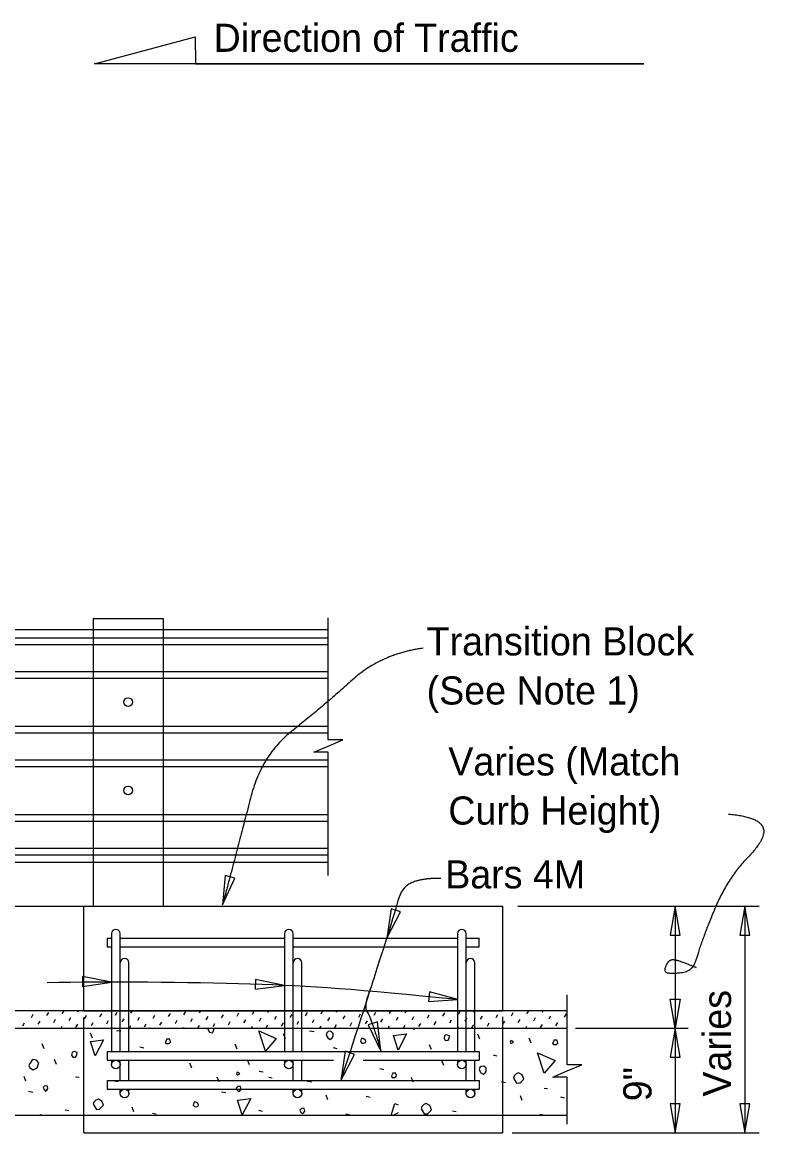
# Model space of a CAD drawing. Extents: x 21526.6 to 21598.7, y 56118.1 to 56155.9.
# Drawn here: x 21561.97 to 21567.29, y 56133.58 to 56141.55 of the extents above; entities that cross this region are included whole.
import ezdxf

# ---------------------------------------------------------------- set-up
doc = ezdxf.new("R2010")
doc.units = 0
for name, color, linetype in [('AdhocPoint_dp', 7, 'Continuous'), ('Border', 7, 'Continuous'), ('Patterning', 7, 'Continuous'), ('PlotBorder_dp', 7, 'Continuous'), ('SheetBorder_dp', 7, 'Continuous'), ('SheetLines_dp', 7, 'Continuous'), ('SubStrConc', 7, 'Continuous'), ('SubStrConc_h', 7, 'Continuous')]:
    doc.layers.add(name, color=color, linetype=linetype)

msp = doc.modelspace()

# ---------------------------------------------------------------- linework, layer by layer
at = {"layer": 'AdhocPoint_dp'}
for p, q in [((21554.3018, 56135.21), (21562.4118, 56135.21)), ((21565.8764, 56134.4601), (21554.3018, 56134.4601)), ((21554.3018, 56134.3351), (21565.8764, 56134.3351)), ((21565.8764, 56133.71), (21559.5217, 56133.71))]:
    msp.add_line(p, q, dxfattribs=at)
at = {"layer": 'Patterning'}
for p, q in [((21562.4788, 56137.2725), (21562.4788, 56135.21)), ((21562.4788, 56137.2725), (21562.9788, 56137.2725)), ((21562.9788, 56137.2725), (21562.9788, 56135.21)), ((21562.0356, 56134.4123), (21562.0485, 56134.4347)), ((21562.1462, 56134.4253), (21562.1592, 56134.4477)), ((21562.2568, 56134.4383), (21562.2695, 56134.4601)), ((21562.3057, 56134.3894), (21562.3186, 56134.4118)), ((21562.3675, 56134.4512), (21562.3726, 56134.4601)), ((21562.4163, 56134.4024), (21562.4293, 56134.4248)), ((21562.5269, 56134.4154), (21562.5399, 56134.4377)), ((21562.6376, 56134.4283), (21562.6505, 56134.4507)), ((21562.6864, 56134.3795), (21562.6994, 56134.4019)), ((21562.7482, 56134.4413), (21562.7591, 56134.4601)), ((21562.797, 56134.3925), (21562.81, 56134.4148)), ((21562.8588, 56134.4542), (21562.8622, 56134.4601)), ((21562.9077, 56134.4054), (21562.9206, 56134.4278)), ((21563.0183, 56134.4184), (21563.0312, 56134.4408)), ((21563.1289, 56134.4313), (21563.1419, 56134.4537)), ((21563.1778, 56134.3825), (21563.1907, 56134.4049)), ((21563.2396, 56134.4443), (21563.2487, 56134.4601)), ((21563.2884, 56134.3955), (21563.3013, 56134.4179)), ((21563.3502, 56134.4573), (21563.3518, 56134.4601)), ((21563.399, 56134.4084), (21563.412, 56134.4308)), ((21563.5097, 56134.4214), (21563.5226, 56134.4438)), ((21563.6203, 56134.4344), (21563.6332, 56134.4568)), ((21563.6691, 56134.3855), (21563.6821, 56134.4079)), ((21563.7309, 56134.4473), (21563.7383, 56134.4601)), ((21563.7798, 56134.3985), (21563.7927, 56134.4209)), ((21563.8904, 56134.4115), (21563.9033, 56134.4338)), ((21564.001, 56134.4244), (21564.014, 56134.4468)), ((21564.1116, 56134.4374), (21564.1246, 56134.4598)), ((21564.1605, 56134.3885), (21564.1734, 56134.4109)), ((21564.2223, 56134.4503), (21564.2279, 56134.4601)), ((21564.2711, 56134.4015), (21564.2841, 56134.4239)), ((21564.3817, 56134.4145), (21564.3947, 56134.4369)), ((21564.4924, 56134.4274), (21564.5053, 56134.4498)), ((21564.5412, 56134.3786), (21564.5542, 56134.401)), ((21564.603, 56134.4404), (21564.6144, 56134.4601)), ((21564.6518, 56134.3916), (21564.6648, 56134.414)), ((21564.7151, 56134.4443), (21564.7243, 56134.4601)), ((21564.764, 56134.3955), (21564.7769, 56134.4179)), ((21564.8258, 56134.4573), (21564.8274, 56134.4601)), ((21564.8746, 56134.4084), (21564.8876, 56134.4308)), ((21564.9852, 56134.4214), (21564.9982, 56134.4438)), ((21565.0959, 56134.4344), (21565.1088, 56134.4568)), ((21565.1447, 56134.3855), (21565.1577, 56134.4079)), ((21565.2065, 56134.4473), (21565.2139, 56134.4601)), ((21565.2553, 56134.3985), (21565.2683, 56134.4209)), ((21565.366, 56134.4115), (21565.3789, 56134.4338)), ((21565.4766, 56134.4244), (21565.4896, 56134.4468)), ((21565.5872, 56134.4374), (21565.6002, 56134.4598)), ((21565.6361, 56134.3885), (21565.649, 56134.4109)), ((21565.6979, 56134.4503), (21565.7035, 56134.4601)), ((21565.7467, 56134.4015), (21565.7597, 56134.4239)), ((21565.8573, 56134.4145), (21565.8703, 56134.4369)), ((21561.9738, 56134.3505), (21561.9867, 56134.3729)), ((21562.0844, 56134.3635), (21562.0974, 56134.3859)), ((21562.145, 56134.3351), (21562.1462, 56134.3371)), ((21562.195, 56134.3765), (21562.208, 56134.3989)), ((21562.2482, 56134.3351), (21562.2568, 56134.35)), ((21562.3545, 56134.3406), (21562.3675, 56134.363)), ((21562.4651, 56134.3536), (21562.4781, 56134.376)), ((21562.5758, 56134.3665), (21562.5887, 56134.3889)), ((21562.6346, 56134.3351), (21562.6376, 56134.3401)), ((21562.7378, 56134.3351), (21562.7482, 56134.353)), ((21562.8459, 56134.3436), (21562.8588, 56134.366)), ((21562.9565, 56134.3566), (21562.9695, 56134.379)), ((21563.0671, 56134.3695), (21563.0801, 56134.3919)), ((21563.1243, 56134.3351), (21563.1289, 56134.3431)), ((21563.2274, 56134.3351), (21563.2396, 56134.3561)), ((21563.3372, 56134.3466), (21563.3502, 56134.369)), ((21563.4479, 56134.3596), (21563.4608, 56134.382)), ((21563.5585, 56134.3726), (21563.5714, 56134.395)), ((21563.6139, 56134.3351), (21563.6203, 56134.3461)), ((21563.718, 56134.3367), (21563.7309, 56134.3591)), ((21563.8286, 56134.3497), (21563.8415, 56134.372)), ((21563.9392, 56134.3626), (21563.9522, 56134.385)), ((21564.0004, 56134.3351), (21564.001, 56134.3362)), ((21564.0499, 56134.3756), (21564.0628, 56134.398)), ((21564.1035, 56134.3351), (21564.1116, 56134.3491)), ((21564.2093, 56134.3397), (21564.2223, 56134.3621)), ((21564.32, 56134.3527), (21564.3329, 56134.3751)), ((21564.4306, 56134.3656), (21564.4435, 56134.388)), ((21564.49, 56134.3351), (21564.4924, 56134.3392)), ((21564.5931, 56134.3351), (21564.603, 56134.3522)), ((21564.703, 56134.3351), (21564.7151, 56134.3561)), ((21564.8128, 56134.3466), (21564.8258, 56134.369)), ((21564.9234, 56134.3596), (21564.9364, 56134.382)), ((21565.0341, 56134.3726), (21565.047, 56134.395)), ((21565.0895, 56134.3351), (21565.0959, 56134.3461)), ((21565.1935, 56134.3367), (21565.2065, 56134.3591)), ((21565.3042, 56134.3497), (21565.3171, 56134.372)), ((21565.4148, 56134.3626), (21565.4278, 56134.385)), ((21565.476, 56134.3351), (21565.4766, 56134.3362)), ((21565.5254, 56134.3756), (21565.5384, 56134.398)), ((21565.5791, 56134.3351), (21565.5872, 56134.3491)), ((21565.6849, 56134.3397), (21565.6979, 56134.3621)), ((21565.7955, 56134.3527), (21565.8085, 56134.3751)), ((21562.4721, 56134.2625), (21562.458, 56134.2979)), ((21562.6448, 56134.3185), (21562.6766, 56134.315)), ((21563.8568, 56134.259), (21563.8427, 56134.2944)), ((21564.0294, 56134.315), (21564.0613, 56134.3114)), ((21565.2489, 56134.2557), (21565.2347, 56134.291)), ((21565.6176, 56134.2282), (21565.6035, 56134.2636)), ((21562.1263, 56134.1877), (21562.1121, 56134.223)), ((21562.8127, 56134.2001), (21562.841, 56134.193)), ((21563.511, 56134.1841), (21563.4968, 56134.2195)), ((21564.1974, 56134.1965), (21564.2257, 56134.1894)), ((21564.903, 56134.1808), (21564.8889, 56134.2161)), ((21562.214, 56134.0752), (21562.1999, 56134.1105)), ((21563.1862, 56134.0491), (21563.172, 56134.0845)), ((21563.5987, 56134.0716), (21563.5846, 56134.107)), ((21564.9908, 56134.0683), (21564.9767, 56134.1036)), ((21565.3441, 56134.1447), (21565.3724, 56134.1376)), ((21563.6672, 56134.0268), (21563.6973, 56134.0215)), ((21564.5329, 56134.0454), (21564.5612, 56134.0384)), ((21561.9955, 56133.9543), (21561.9831, 56133.9879)), ((21562.3519, 56133.9868), (21562.3767, 56133.9832)), ((21562.6277, 56133.9585), (21562.6578, 56133.9532)), ((21563.3802, 56133.9508), (21563.3678, 56133.9844)), ((21563.7366, 56133.9832), (21563.7614, 56133.9797)), ((21564.0124, 56133.955), (21564.0424, 56133.9497)), ((21564.7722, 56133.9474), (21564.7598, 56133.981)), ((21565.4045, 56133.9516), (21565.4345, 56133.9463)), ((21562.0143, 56133.8825), (21562.0443, 56133.8772)), ((21563.399, 56133.8789), (21563.429, 56133.8736)), ((21564.1609, 56133.8206), (21564.1485, 56133.8542)), ((21564.4349, 56133.8471), (21564.4632, 56133.8401)), ((21565.5529, 56133.8173), (21565.5406, 56133.8508)), ((21565.7105, 56133.9057), (21565.7353, 56133.9022)), ((21565.8269, 56133.8438), (21565.8552, 56133.8367)), ((21562.7705, 56133.7357), (21562.7581, 56133.7693)), ((21562.2777, 56133.7499), (21562.3042, 56133.7446)), ((21562.9035, 56133.7251), (21562.93, 56133.7198)), ((21563.1969, 56133.71), (21563.1963, 56133.7116)), ((21563.6624, 56133.7464), (21563.6889, 56133.7411)), ((21564.2882, 56133.7216), (21564.3147, 56133.7163)), ((21565.0544, 56133.743), (21565.0809, 56133.7377)), ((21565.6802, 56133.7183), (21565.7067, 56133.713))]:
    msp.add_line(p, q, dxfattribs=at)
for points in [[(21563.3008, 56134.3351), (21563.2988, 56134.3291), (21563.3024, 56134.322)], [(21563.3024, 56134.322), (21563.3112, 56134.3061), (21563.3324, 56134.3026), (21563.3413, 56134.3185), (21563.3448, 56134.3326), (21563.3424, 56134.3351)], [(21564.7764, 56134.3351), (21564.7744, 56134.3291), (21564.7779, 56134.322)], [(21562.4929, 56134.1357), (21562.4593, 56134.24), (21562.553, 56134.2524), (21562.4929, 56134.1357)], [(21563.0001, 56134.2248), (21563.0213, 56134.2248), (21563.0319, 56134.2354), (21563.0266, 56134.2549), (21563.0036, 56134.2566), (21563.0001, 56134.246), (21562.9948, 56134.2372), (21563.0001, 56134.2248), (21562.9965, 56134.2283)], [(21563.7121, 56134.1696), (21563.6644, 56134.3163), (21563.7899, 56134.2615), (21563.7121, 56134.1696)], [(21564.1486, 56134.2859), (21564.1592, 56134.2647), (21564.1769, 56134.2541), (21564.191, 56134.2647), (21564.1981, 56134.2753), (21564.1981, 56134.2965), (21564.1822, 56134.3124), (21564.1627, 56134.3106), (21564.1539, 56134.3018), (21564.1486, 56134.2859)], [(21564.4044, 56134.2281), (21564.4168, 56134.2263), (21564.4292, 56134.2316), (21564.4327, 56134.2423), (21564.4274, 56134.2511), (21564.4168, 56134.2582), (21564.4044, 56134.2635), (21564.3973, 56134.2493), (21564.3938, 56134.2387), (21564.4044, 56134.2281)], [(21564.6643, 56134.1779), (21564.6307, 56134.2822), (21564.7244, 56134.2945), (21564.6643, 56134.1779)], [(21564.9933, 56134.2627), (21565.0022, 56134.2468), (21565.0216, 56134.2485), (21565.0304, 56134.2609), (21565.0322, 56134.2803), (21565.0198, 56134.2856), (21565.011, 56134.2874), (21565.0004, 56134.2839), (21564.9968, 56134.2803), (21564.9933, 56134.2627)], [(21565.4713, 56134.2251), (21565.4908, 56134.2339), (21565.4837, 56134.241), (21565.4713, 56134.2463), (21565.466, 56134.2339), (21565.4713, 56134.2251)], [(21565.7768, 56134.2179), (21565.798, 56134.2179), (21565.8086, 56134.2285), (21565.8033, 56134.248), (21565.7804, 56134.2497), (21565.7768, 56134.2391), (21565.7715, 56134.2303), (21565.7768, 56134.2179), (21565.7733, 56134.2215)], [(21562.3237, 56134.1423), (21562.3325, 56134.1264), (21562.3519, 56134.1282), (21562.3608, 56134.1406), (21562.3625, 56134.16), (21562.3502, 56134.1653), (21562.3413, 56134.1671), (21562.3307, 56134.1636), (21562.3272, 56134.16), (21562.3237, 56134.1423)], [(21562.0238, 56134.0498), (21562.0467, 56134.0374), (21562.0768, 56134.0498), (21562.0892, 56134.0869), (21562.0715, 56134.1046), (21562.0485, 56134.1099), (21562.0379, 56134.1028), (21562.0255, 56134.0834), (21562.0167, 56134.0675), (21562.0238, 56134.0498)], [(21565.7117, 56134.0122), (21565.664, 56134.1589), (21565.7895, 56134.1041), (21565.7117, 56134.0122)], [(21563.5103, 56133.998), (21563.5298, 56134.0068), (21563.5227, 56134.0139), (21563.5103, 56134.0192), (21563.505, 56134.0068), (21563.5103, 56133.998)], [(21564.6215, 56133.9816), (21564.6427, 56133.9816), (21564.6533, 56133.9922), (21564.648, 56134.0116), (21564.625, 56134.0134), (21564.6215, 56134.0028), (21564.6162, 56133.994), (21564.6215, 56133.9816), (21564.618, 56133.9851)], [(21565.2454, 56134.0365), (21565.256, 56134.0152), (21565.2736, 56134.0046), (21565.2878, 56134.0152), (21565.2948, 56134.0259), (21565.2948, 56134.0471), (21565.2789, 56134.063), (21565.2595, 56134.0612), (21565.2507, 56134.0524), (21565.2454, 56134.0365)], [(21565.4907, 56133.9776), (21565.5137, 56133.9404), (21565.5366, 56133.9422), (21565.5455, 56133.9511), (21565.5649, 56133.9705), (21565.5526, 56134.0005), (21565.5278, 56134.0147), (21565.5101, 56134.0076), (21565.496, 56133.9935), (21565.4907, 56133.9776)], [(21562.1257, 56133.8949), (21562.1363, 56133.8842), (21562.1469, 56133.8913), (21562.1539, 56133.9019), (21562.1504, 56133.9196), (21562.1416, 56133.9214), (21562.1292, 56133.9196), (21562.1186, 56133.909), (21562.1257, 56133.8949)], [(21563.5103, 56133.8913), (21563.5209, 56133.8807), (21563.5316, 56133.8878), (21563.5386, 56133.8984), (21563.5351, 56133.9161), (21563.5262, 56133.9178), (21563.5139, 56133.9161), (21563.5033, 56133.9055), (21563.5103, 56133.8913)], [(21562.4785, 56133.7897), (21562.5015, 56133.7526), (21562.5245, 56133.7544), (21562.5333, 56133.7632), (21562.5528, 56133.7827), (21562.5404, 56133.8127), (21562.5156, 56133.8269), (21562.498, 56133.8198), (21562.4838, 56133.8056), (21562.4785, 56133.7897)], [(21563.2051, 56133.7723), (21563.2175, 56133.7705), (21563.2299, 56133.7758), (21563.2334, 56133.7864), (21563.2281, 56133.7952), (21563.2175, 56133.8023), (21563.2051, 56133.8076), (21563.1981, 56133.7935), (21563.1945, 56133.7829), (21563.2051, 56133.7723)], [(21563.547, 56133.7141), (21563.5134, 56133.8184), (21563.6071, 56133.8308), (21563.547, 56133.7141)], [(21564.6141, 56133.71), (21564.6405, 56133.7959), (21564.6652, 56133.7861)], [(21564.8288, 56133.7569), (21564.8518, 56133.7198), (21564.8748, 56133.7216), (21564.8836, 56133.7304), (21564.9031, 56133.7499), (21564.8907, 56133.7799), (21564.8659, 56133.794), (21564.8483, 56133.787), (21564.8341, 56133.7728), (21564.8288, 56133.7569)], [(21562.1099, 56133.71), (21562.1009, 56133.7145), (21562.0934, 56133.71)], [(21563.4875, 56133.71), (21563.4856, 56133.711), (21563.484, 56133.71)], [(21563.9669, 56133.7339), (21563.9775, 56133.7233), (21563.9881, 56133.7304), (21563.9951, 56133.741), (21563.9916, 56133.7586), (21563.9828, 56133.7604), (21563.9704, 56133.7586), (21563.9598, 56133.748), (21563.9669, 56133.7339)], [(21564.6652, 56133.7277), (21564.6258, 56133.71)], [(21564.8796, 56133.7067), (21564.8777, 56133.7077), (21564.876, 56133.7067)]]:
    msp.add_lwpolyline(points, dxfattribs=at)
at = {"layer": 'PlotBorder_dp'}
for p, q in [((21562.4876, 56141.2478), (21563.2092, 56141.4395)), ((21563.2092, 56141.4395), (21563.2109, 56141.2478)), ((21566.2979, 56141.2478), (21562.4876, 56141.2478)), ((21563.2109, 56141.2478), (21566.4242, 56141.2478)), ((21566.4242, 56141.2478), (21566.2979, 56141.2478)), ((21565.5209, 56135.21), (21567.2532, 56135.21)), ((21566.6495, 56135.21), (21566.6495, 56133.585)), ((21567.1495, 56135.21), (21567.1495, 56133.585)), ((21565.9364, 56134.335), (21566.742, 56134.335)), ((21565.4809, 56133.585), (21567.2532, 56133.585))]:
    msp.add_line(p, q, dxfattribs=at)
for points in [[(21564.1633, 56135.429), (21564.1633, 56136.3122), (21564.0599, 56136.3122), (21564.1633, 56136.3572), (21564.2666, 56136.4022), (21564.1633, 56136.4022), (21564.1633, 56137.2752)], [(21565.8764, 56133.6472), (21565.8764, 56133.9832), (21565.7731, 56133.9832), (21565.8764, 56134.0282), (21565.9797, 56134.0732), (21565.8764, 56134.0732), (21565.8764, 56134.5731)]]:
    msp.add_lwpolyline(points, dxfattribs=at)
for points in [[(21563.4053, 56135.2188), (21563.4928, 56135.4111), (21563.4245, 56135.4291)], [(21566.6495, 56135.21), (21566.6142, 56135.0017), (21566.6848, 56135.0017)], [(21567.1495, 56135.21), (21567.1142, 56135.0017), (21567.1848, 56135.0017)], [(21564.5839, 56134.9808), (21564.6819, 56135.1679), (21564.6148, 56135.1898)], [(21562.6093, 56134.6644), (21562.4019, 56134.7045), (21562.4003, 56134.634)], [(21563.8483, 56134.6403), (21563.6418, 56134.6846), (21563.6388, 56134.6141)], [(21565.0916, 56134.5393), (21564.8879, 56134.5955), (21564.8808, 56134.5253)], [(21566.6495, 56134.335), (21566.6142, 56134.5432), (21566.6848, 56134.5432)], [(21564.5411, 56134.1696), (21564.5162, 56134.3794), (21564.4485, 56134.3595)], [(21566.6495, 56134.335), (21566.6142, 56134.1267), (21566.6848, 56134.1267)], [(21564.2526, 56133.9599), (21564.3506, 56134.147), (21564.2835, 56134.1689)], [(21566.6495, 56133.585), (21566.6848, 56133.7933), (21566.6142, 56133.7933)], [(21567.1495, 56133.585), (21567.1848, 56133.7933), (21567.1142, 56133.7933)]]:
    msp.add_lwpolyline(points, close=True, dxfattribs=at)
for points, degree in [([(21564.8436, 56137.0585), (21564.5421, 56137.0183), (21564.1187, 56136.6348), (21563.685, 56136.2922), (21563.5309, 56135.6927), (21563.4053, 56135.2188)], 2), ([(21567.0317, 56135.8695), (21567.2405, 56135.8519), (21567.3147, 56135.7056), (21567.0236, 56135.4087), (21566.8353, 56134.952), (21566.7782, 56134.7407), (21566.6298, 56134.7236), (21566.5671, 56134.735), (21566.6013, 56134.8264), (21566.6698, 56134.8264), (21566.8011, 56134.7693)], 2), ([(21564.9691, 56135.4078), (21564.8456, 56135.4112), (21564.6854, 56135.3477), (21564.6319, 56135.124), (21564.2525, 56133.9599)], 2), ([(21565.0915, 56134.5393), (21564.3611, 56134.6135), (21563.7396, 56134.6602), (21562.5755, 56134.6687), (21562.1492, 56134.661)], 3), ([(21564.4705, 56134.6317), (21564.412, 56134.4912), (21564.4698, 56134.4123), (21564.5411, 56134.1696)], 2)]:
    msp.add_open_spline(points, degree=degree, dxfattribs=at)
at = {"layer": 'SheetBorder_dp'}
for p, q in [((21564.1633, 56137.1891), (21552.8484, 56137.1891)), ((21552.8484, 56137.1336), (21564.1633, 56137.1336)), ((21552.8484, 56137.0853), (21564.1633, 56137.0853)), ((21552.8484, 56136.8925), (21564.1633, 56136.8925)), ((21552.8484, 56136.8443), (21564.1633, 56136.8443)), ((21552.8484, 56136.5003), (21564.1633, 56136.5003)), ((21552.8484, 56136.4521), (21564.1633, 56136.4521)), ((21552.8484, 56136.2593), (21564.1633, 56136.2593)), ((21552.8484, 56136.2112), (21564.1633, 56136.2112)), ((21552.8484, 56135.8672), (21564.1633, 56135.8672)), ((21552.8484, 56135.819), (21564.1633, 56135.819)), ((21552.8484, 56135.6262), (21564.1633, 56135.6262)), ((21552.8484, 56135.5779), (21564.1633, 56135.5779)), ((21564.1633, 56135.5224), (21552.8484, 56135.5224))]:
    msp.add_line(p, q, dxfattribs=at)
for centre in [(21562.7288, 56136.6724), (21562.7288, 56136.0393)]:
    msp.add_circle(centre, 0.0312, dxfattribs=at)
at = {"layer": 'SheetLines_dp'}
for p, q in [((21562.5785, 56134.9808), (21562.6097, 56134.9808)), ((21562.5785, 56134.9808), (21562.5785, 56134.9183)), ((21562.6097, 56135.0121), (21562.6097, 56134.1683)), ((21562.6722, 56134.1683), (21562.6722, 56135.0121)), ((21562.6722, 56134.9808), (21563.8493, 56134.9808)), ((21563.8493, 56135.0121), (21563.8493, 56134.1683)), ((21563.9118, 56134.1683), (21563.9118, 56135.0121)), ((21563.9118, 56134.9808), (21565.0889, 56134.9808)), ((21565.0889, 56135.0121), (21565.0889, 56134.1683)), ((21565.1514, 56134.1683), (21565.1514, 56135.0121)), ((21565.1514, 56134.9808), (21565.2451, 56134.9808)), ((21565.2451, 56134.9183), (21565.2451, 56134.9808)), ((21562.5785, 56134.9183), (21562.6097, 56134.9183)), ((21562.6722, 56134.9183), (21563.8493, 56134.9183)), ((21563.9118, 56134.9183), (21565.0889, 56134.9183)), ((21565.1514, 56134.9183), (21565.2451, 56134.9183)), ((21562.7347, 56134.1683), (21562.7347, 56134.8038)), ((21563.9743, 56134.1683), (21563.9743, 56134.8038)), ((21565.2139, 56134.1683), (21565.2139, 56134.8038)), ((21562.5785, 56134.1683), (21562.5785, 56134.1058)), ((21562.5785, 56134.1683), (21565.2451, 56134.1683)), ((21565.2451, 56134.1683), (21565.2451, 56134.1058)), ((21562.5785, 56134.1058), (21564.1999, 56134.1058)), ((21562.6097, 56134.1058), (21562.6097, 56134.0745)), ((21562.6722, 56133.9599), (21562.6722, 56134.1058)), ((21562.7347, 56133.9599), (21562.7347, 56134.1058)), ((21563.8493, 56134.1058), (21563.8493, 56134.0745)), ((21563.9118, 56133.9599), (21563.9118, 56134.1058)), ((21563.9743, 56133.9599), (21563.9743, 56134.1058)), ((21564.4139, 56134.1058), (21565.2451, 56134.1058)), ((21565.0889, 56134.1058), (21565.0889, 56134.0745)), ((21565.1514, 56133.9599), (21565.1514, 56134.1058)), ((21565.2139, 56133.9599), (21565.2139, 56134.1058)), ((21562.5785, 56133.9599), (21562.5785, 56133.8975)), ((21562.5785, 56133.9599), (21565.2451, 56133.9599)), ((21565.2451, 56133.9599), (21565.2451, 56133.8975)), ((21562.5785, 56133.8975), (21565.2451, 56133.8975)), ((21562.6722, 56133.8662), (21562.6722, 56133.8975)), ((21562.7347, 56133.8662), (21562.7347, 56133.8975)), ((21563.9118, 56133.8662), (21563.9118, 56133.8975)), ((21563.9743, 56133.8662), (21563.9743, 56133.8975)), ((21565.1514, 56133.8662), (21565.1514, 56133.8975)), ((21565.2139, 56133.8662), (21565.2139, 56133.8975))]:
    msp.add_line(p, q, dxfattribs=at)
for centre in [(21562.6409, 56134.0745), (21563.8805, 56134.0745), (21565.1201, 56134.0745), (21562.7034, 56133.8662), (21563.943, 56133.8662), (21565.1826, 56133.8662)]:
    msp.add_circle(centre, 0.0312, dxfattribs=at)
for centre, radius, start, end in [((21562.6409, 56135.0121), 0.0312, 0, 180), ((21563.8805, 56135.0121), 0.0312, 0, 180), ((21565.1201, 56135.0121), 0.0312, 0, 180), ((21562.7034, 56134.8038), 0.0312, 0, 180), ((21563.943, 56134.8038), 0.0312, 0, 180), ((21565.1826, 56134.8038), 0.0312, 0, 180), ((21562.8709, 56133.1683), 1, 90, 90.00000277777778)]:
    msp.add_arc(centre, radius, start, end, dxfattribs=at)
at = {"layer": 'SubStrConc'}
for p, q in [((21562.4118, 56134.46), (21562.4118, 56135.21)), ((21562.4118, 56135.21), (21565.4118, 56135.21)), ((21565.4118, 56135.21), (21565.4118, 56134.46))]:
    msp.add_line(p, q, dxfattribs=at)
at = {"layer": 'SubStrConc_h'}
for p, q in [((21562.4118, 56134.46), (21565.4118, 56134.46)), ((21562.4118, 56133.585), (21562.4118, 56134.4115)), ((21565.4118, 56134.417), (21565.4118, 56133.585)), ((21562.4118, 56133.585), (21565.4118, 56133.585))]:
    msp.add_line(p, q, dxfattribs=at)

# ---------------------------------------------------------------- texts
at = {"layer": 'Border'}
for s, rotation, p in [('Direction of Traffic', 359.99977, (21563.3411, 56141.3331)), ('Varies', 90, (21567.0502, 56133.8443)), ('9"', 90, (21566.4798, 56133.8109))]:
    msp.add_text(s, height=0.2016, rotation=rotation, dxfattribs=at).set_placement(p)
msp.add_text('Bars 4M', height=0.2016, dxfattribs=at).set_placement((21565.0015, 56135.3365))
at = {"layer": 'PlotBorder_dp'}
for s, p in [('Transition Block', (21564.8684, 56137.0067)), ('(See Note 1)', (21564.8684, 56136.6547)), ('Varies (Match', (21565.0237, 56136.1462)), ('Curb Height)', (21565.0237, 56135.7942))]:
    msp.add_text(s, height=0.2016, dxfattribs=at).set_placement(p)

doc.saveas('drawing.dxf')
